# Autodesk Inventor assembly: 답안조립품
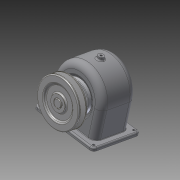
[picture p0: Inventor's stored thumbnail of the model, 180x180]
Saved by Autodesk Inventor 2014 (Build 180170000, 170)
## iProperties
Created: 2016-01
Part Number: 답안조립품
Document SubType Name: Assembly
Designer: Owner
Author: Owner
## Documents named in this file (16)
- C:\Documents and Settings\Owner\바탕 화면\460106V1021\답안조립품.iam
- C:\Documents and Settings\Owner\바탕 화면\460106V1021\1. 본체.ipt
- C:\Documents and Settings\Owner\바탕 화면\460106V1021\뒤커버.ipt
- C:\Documents and Settings\Owner\바탕 화면\460106V1021\볼트 M3 x 8.ipt
- C:\Documents and Settings\Owner\바탕 화면\460106V1021\베어링 6203.ipt
- C:\Documents and Settings\Owner\바탕 화면\460106V1021\축.ipt
- C:\Documents and Settings\Owner\바탕 화면\460106V1021\부시1.ipt
- C:\Documents and Settings\Owner\바탕 화면\460106V1021\키 - 6 x 6 x 22.ipt
- C:\Documents and Settings\Owner\바탕 화면\460106V1021\스퍼기어.ipt
- C:\Documents and Settings\Owner\바탕 화면\460106V1021\앞커버.ipt
- C:\Documents and Settings\Owner\바탕 화면\460106V1021\볼트 M3 x 10.ipt
- C:\Documents and Settings\Owner\바탕 화면\460106V1021\오일씰 28 40 8.ipt
- C:\Documents and Settings\Owner\바탕 화면\460106V1021\부시2.ipt
- C:\Documents and Settings\Owner\바탕 화면\460106V1021\키 - 5 x 5 x 18.ipt
- C:\Documents and Settings\Owner\바탕 화면\460106V1021\V-벨트풀리.ipt
- C:\Documents and Settings\Owner\바탕 화면\460106V1021\멈춤나사 - M4x10.ipt
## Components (10 placed, 4 different names)
1. 1. 본체:1
2. V-벨트풀리:1 — 각도:4
3. ISO 4762 M3 x 8:1
4. ISO 4762 M3 x 8:2
5. ISO 4762 M3 x 8:3
6. ISO 4762 M3 x 8:4
7. ISO 4762 M3 x 10:1
8. ISO 4762 M3 x 10:2
9. ISO 4762 M3 x 10:3
10. ISO 4762 M3 x 10:4
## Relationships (1: Angle 1)
- 각도:4 [Angle]: V-벨트풀리:1
